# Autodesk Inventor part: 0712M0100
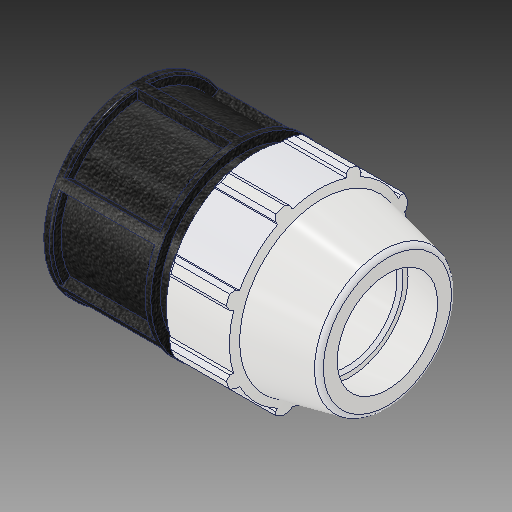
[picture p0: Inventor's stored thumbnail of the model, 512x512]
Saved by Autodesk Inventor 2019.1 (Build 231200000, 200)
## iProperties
Created: 2017-02
Part Number: 0712M0100
Material: PVC-Piping
Description: PLASSON END PLUG 1''
Document SubType Name: Modeling
Designer: KIM
Mass: 92.6774 g
Surface Area: 199.44 cm^2
Volume: 66.1981 cm^3
Density: 1.4 g/cm^3
Appearance: PTFE
Author: Кирилл
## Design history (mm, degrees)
derived "0712M0.ipt"
feature "Solid1::0712M0.ipt"
tag "TaggingFeature1"
body "Solid1"
other parameters: "d2" = 33.3, "d4" = 12.446, "d5" = 21.7805, "d7" = 64.008, "d8" = 54.4068, "d9" = 12.446, "d11" = 2.4892, "d12" = 54.4068, "d13" = 120 deg, "d15" = 12 deg, "d16" = 60.8076, "d18" = 1.665, "d19" = 35 deg, "d20" = 17.5 deg, "d21" = 59.52744, "d23" = 0, "d25" = 360 deg, "d27" = 1.28016, "d34" = 3.2004, "d36" = 0, "d42" = 21.7805, "d43" = 1.92024, "d46" = 0.999, "d53" = 0.666, "d55" = 360 deg, "d59" = 30.4927, "d64" = 87.122, "d66" = 6.4008, "d67" = 3.2004, "d68" = 81.026, "d70" = 54.4068, "d_" = 33.3, "E_" = 64.008, "H_" = 87.122, "l_" = 81.026
